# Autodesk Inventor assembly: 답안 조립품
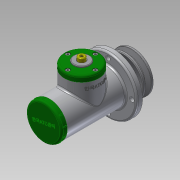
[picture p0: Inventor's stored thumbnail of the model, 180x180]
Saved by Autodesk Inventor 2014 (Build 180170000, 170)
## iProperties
Created: 2016-08
Part Number: 답안 조립품
Document SubType Name: Assembly
Designer: user
Author: user
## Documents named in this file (24)
- C:\Users\user\Desktop\460808V1002\답안 조립품.iam
- C:\Users\user\Desktop\460808V1002\본체.ipt
- C:\Users\user\Desktop\460808V1002\사이드 커버.ipt
- 사이드 커버.ipt
- C:\Users\user\Desktop\460808V1002\탑 커버.ipt
- 탑 커버.ipt
- C:\Users\user\Desktop\460808V1002\볼트 M4 x 12.ipt
- C:\Users\user\Desktop\460808V1002\탑 부시.ipt
- C:\Users\user\Desktop\460808V1002\편심축.ipt
- C:\Users\user\Desktop\460808V1002\베어링 15 x 35 x 11.ipt
- C:\Users\user\Desktop\460808V1002\부시1.ipt
- C:\Users\user\Desktop\460808V1002\멈춤링 35x1.6.ipt
- C:\Users\user\Desktop\460808V1002\부시2.ipt
- C:\Users\user\Desktop\460808V1002\와셔 10x21.ipt
- C:\Users\user\Desktop\460808V1002\너트 M10.ipt
- C:\Users\user\Desktop\460808V1002\멈춤링 15 x 1.ipt
- C:\Users\user\Desktop\460808V1002\키 4 x 4 x 18.ipt
- C:\Users\user\Desktop\460808V1002\오일 실 15 25 7.ipt
- C:\Users\user\Desktop\460808V1002\V-벨트풀리.ipt
- C:\Users\user\Desktop\460808V1002\와셔 4x16.ipt
- C:\Users\user\Desktop\460808V1002\볼트 M4 x 10.ipt
- C:\Users\user\Desktop\460808V1002\슬라이더.ipt
- C:\Users\user\Desktop\460808V1002\링크.ipt
- C:\Users\user\Desktop\460808V1002\클래스터 핀 6 x 24.ipt
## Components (6 placed, 3 different names)
1. V-벨트풀리:1 — Mate:32, Mate:33, Mate:34
2. ISO 4017 M4 x 10:1 — Insert:3, Angle:10
3. ISO 4762 M4 x 12:1 — Insert:1
4. ISO 4762 M4 x 12:2
5. ISO 4762 M4 x 12:3
6. ISO 4762 M4 x 12:4
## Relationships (6: Mate 3, Insert 2, Angle 1)
- Insert:1: ISO 4762 M4 x 12:1
- Mate:32: V-벨트풀리:1
- Mate:33: V-벨트풀리:1
- Mate:34: V-벨트풀리:1
- Insert:3: ISO 4017 M4 x 10:1
- Angle:10: ISO 4017 M4 x 10:1
